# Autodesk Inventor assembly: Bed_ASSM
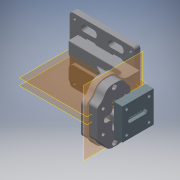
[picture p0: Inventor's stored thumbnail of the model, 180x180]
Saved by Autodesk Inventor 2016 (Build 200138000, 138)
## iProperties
Created: 2015-11
Part Number: Bed_ASSM
Document SubType Name: Assembly
Designer: John
Author: John
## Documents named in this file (5)
- D:\3D Printer Designs\John Ledden Designs\DLP Printer\V0-4\Bed_ASSM.iam
- D:\3D Printer Designs\John Ledden Designs\DLP Printer\V0-4\Bed_to_ZAxis_Bracket.ipt
- D:\3D Printer Designs\John Ledden Designs\DLP Printer\PlateMount.ipt
- D:\3D Printer Designs\John Ledden Designs\DLP Printer\Plate2.ipt
- D:\3D Printer Designs\John Ledden Designs\DLP Printer\V0-4\BedSpacer.ipt
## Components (4 placed, 4 different names)
1. Bed_to_ZAxis_Bracket_1078
2. PlateMount:1 — Flush:1, Flush:2
3. Plate2:1 — Flush:1, Flush:2, Flush:3, Flush:4, Flush:5
4. BedSpacer:1 — Flush:3, Flush:4, Flush:5
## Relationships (5: Flush 5)
- Flush:1: PlateMount:1 ↔ Plate2:1
- Flush:2: PlateMount:1 ↔ Plate2:1
- Flush:3: Plate2:1 ↔ BedSpacer:1
- Flush:4: Plate2:1 ↔ BedSpacer:1
- Flush:5: Plate2:1 ↔ BedSpacer:1
